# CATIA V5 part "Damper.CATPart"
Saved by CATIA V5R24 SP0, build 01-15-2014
Part number: Damper
Bounding box of the stored display mesh (mm): x -51.219 to 5, y -12.637 to 12.637, z -12.778 to 12.778
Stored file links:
  \\cdl-main\FTPSERVER\Minsik\2016\2\Damper.CATPart
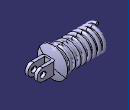
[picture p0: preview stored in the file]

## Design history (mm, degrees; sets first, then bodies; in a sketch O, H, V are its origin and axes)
Set1
  Sketch1 on zx-plane, origin (0, 0, 0), H (-1, 0, 0), V (0, 0, 1)
    point P1 (0, 5)
    line L1 (0, 5) -> (10.5, 5)
    line L2 (10.5, 5) -> (10.5, -5)
    line L3 (10.5, -5) -> (0, -5)
    point P4 (0, -5)
    arc A1 centre (0, 0) radius 5 from (0, -5) to (0, 5) cw
    point P5 (0, 0)
    circle A2 centre (0, 0) radius 2.5
    radius A1 = 5
    distance V L2 = 10.5
    radius A2 = 2.5
    coincidence: P1 V, P4 V, P5 O
    horizontal: L1 H, L3 H
    vertical: L2 V
    tangency: A1 L1, A1 L3
Body1 (main body)
  Pad1: profile Sketch1, direction (0, 1, 0), length 5, mirrored extent
  Sketch2 on xy-plane, origin (0, 0, 0), H (1, 0, 0), V (0, 1, 0)
    line L1 (-9, 2.5) -> (14.0864, 2.5)
    line L2 (14.0864, -2.5) -> (-9, -2.5)
    line L3 (-9, -2.5) -> (-9, 2.5)
    reference projected line E1 (-10.5, -5) -> (-10.5, 5) from edge [face of Pad1 from Sketch1.L1 | face of Pad1 from Sketch1.L2]
    distance L1 L2 = 5
    distance L3 E1 = 1.5
    horizontal: L1 H, L2 H
    vertical: L3 V
    symmetry: L1 L2 H
  Pocket1: profile Sketch2, direction (0, 0, -1), length 13, mirrored extent
  Fillet1: radius 1.5, on edge [face of Pad1 from Sketch1.L2 | end face of Pad1]; edge [start face of Pad1 | face of Pad1 from Sketch1.L2]
  Sketch3 on xy-plane, origin (0, 0, 0), H (1, 0, 0), V (0, 1, 0)
    arc A1 centre (-42.5, 0) radius 32 from (-10.5, 0) to (-13.0397, 12.4936) ccw
    point P1 (-42.5, 0)
    point P2 (-10.5, 0)
    axis line L1 (42.8276, 0) -> (-90.4796, 0)
    point P3 (42.8276, 0)
    reference projected line E1 (-10.5, -5) -> (-10.5, 5) from edge [face of Pad1 from Sketch1.L1 | face of Pad1 from Sketch1.L2]
    line L2 (-14, 12.2984) -> (-14, 0)
    point P5 (-14, 0)
    arc A2 centre (-13.5, 12.2984) radius 0.5 from (-14, 12.2984) to (-13.0397, 12.4936) cw
    radius A1 = 32
    distance L2 P2 = 3.5
    radius A2 = 0.5
    coincidence: P1 H, P2 H, P3 H, P2 E1, P5 L1
    horizontal: L1 H
    vertical: L2 V
    tangency: A2 L2, A2 A1
  Shaft1: profile Sketch3, axis Sketch3.L1, angle 360
  Sketch4 on face of Shaft1 from Sketch3.L2, origin (-14, 0, 0), H (0, -1, 0), V (0, 0, 1)
    circle A1 centre (0, 0) radius 5
    radius A1 = 5
  Pad2: profile Sketch4, direction (-1, 0, 0), length 36
  Point1: type OnPlane, Support zx-plane, H 14, V 9, Direction (-1, 0, 0)
  Helix1: Pitch 4, Height 36, TaperAngle 0, Revolutions 1, Direction X axis, RefPoint Point1
  Sketch5 on zx-plane, origin (0, 0, 0), H (-1, 0, 0), V (0, 0, 1)
    circle A1 centre (14, 9) radius 1.25
    point P1 (14, 9)
    reference projected point E1 (14, 9) from Point1
    radius A1 = 1.25
    coincidence: P1 E1
  Rib1: profile Sketch5, centre curve Helix1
